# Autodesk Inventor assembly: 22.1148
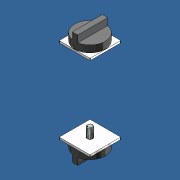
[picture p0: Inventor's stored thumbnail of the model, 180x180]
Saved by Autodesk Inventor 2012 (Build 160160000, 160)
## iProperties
Created: 2014-04
Part Number: 22.1148
Document SubType Name: Assembly
Designer: Admin
Description: INTERNAL ANGLE FOR FOLDING DOORS
Vendor: S
Stock Number: 22.1148 INTERNAL ANGLE FOR FOLDING DOORS
Author: Admin
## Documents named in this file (4)
- C:\Andys Backup Data\ANDY'S INVENTOR\INVENTOR LIBRARIES\PARTS LIBRARY\PREASSEMBLED ELEMENTS FOR LIFTING AND SLIDING DOORS\22.1148 INTERNAL ANGLE FOR FOLDING DOORS.iam
- C:\Andys Backup Data\ANDY'S INVENTOR\INVENTOR LIBRARIES\PARTS LIBRARY\PREASSEMBLED ELEMENTS FOR LIFTING AND SLIDING DOORS\SUBCOMPONENTS\22.1148_1 FOLDING DOOR SLIDE ELE.ipt
- C:\Andys Backup Data\ANDY'S INVENTOR\INVENTOR LIBRARIES\PARTS LIBRARY\END CAPS\SUBCOMPONENTS\22.1067_2 END CAP 45X45 AL.ipt
- C:\Andys Backup Data\ANDY'S INVENTOR\INVENTOR LIBRARIES\PARTS LIBRARY\FASTENING ELEMENTS\SCREWS CAP\SHCS M8X16 HIGH HEAD.ipt
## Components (6 placed, 3 different names)
1. 22.1148_1 FOLDING DOOR SLIDE ELE:1 — Mate:1, Angle:1, Angle:2, Insert:3
2. 22.1148_1 FOLDING DOOR SLIDE ELE:2 — Mate:1, Angle:1, Angle:2, Insert:4
3. 22.1067_2 END CAP 45X45 AL:1 — Insert:1, Insert:3, Angle:3
4. 22.1067_2 END CAP 45X45 AL:2 — Insert:2, Insert:4, Angle:3
5. SHCS M8X16 HIGH HEAD:1 — Insert:1
6. SHCS M8X16 HIGH HEAD:2 — Insert:2
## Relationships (8: Insert 4, Angle 3, Mate 1)
- Mate:1: 22.1148_1 FOLDING DOOR SLIDE ELE:1 ↔ 22.1148_1 FOLDING DOOR SLIDE ELE:2
- Angle:1: 22.1148_1 FOLDING DOOR SLIDE ELE:1 ↔ 22.1148_1 FOLDING DOOR SLIDE ELE:2
- Angle:2: 22.1148_1 FOLDING DOOR SLIDE ELE:1 ↔ 22.1148_1 FOLDING DOOR SLIDE ELE:2
- Insert:1: 22.1067_2 END CAP 45X45 AL:1 ↔ SHCS M8X16 HIGH HEAD:1
- Insert:2: 22.1067_2 END CAP 45X45 AL:2 ↔ SHCS M8X16 HIGH HEAD:2
- Insert:3: 22.1148_1 FOLDING DOOR SLIDE ELE:1 ↔ 22.1067_2 END CAP 45X45 AL:1
- Insert:4: 22.1148_1 FOLDING DOOR SLIDE ELE:2 ↔ 22.1067_2 END CAP 45X45 AL:2
- Angle:3: 22.1067_2 END CAP 45X45 AL:1 ↔ 22.1067_2 END CAP 45X45 AL:2
